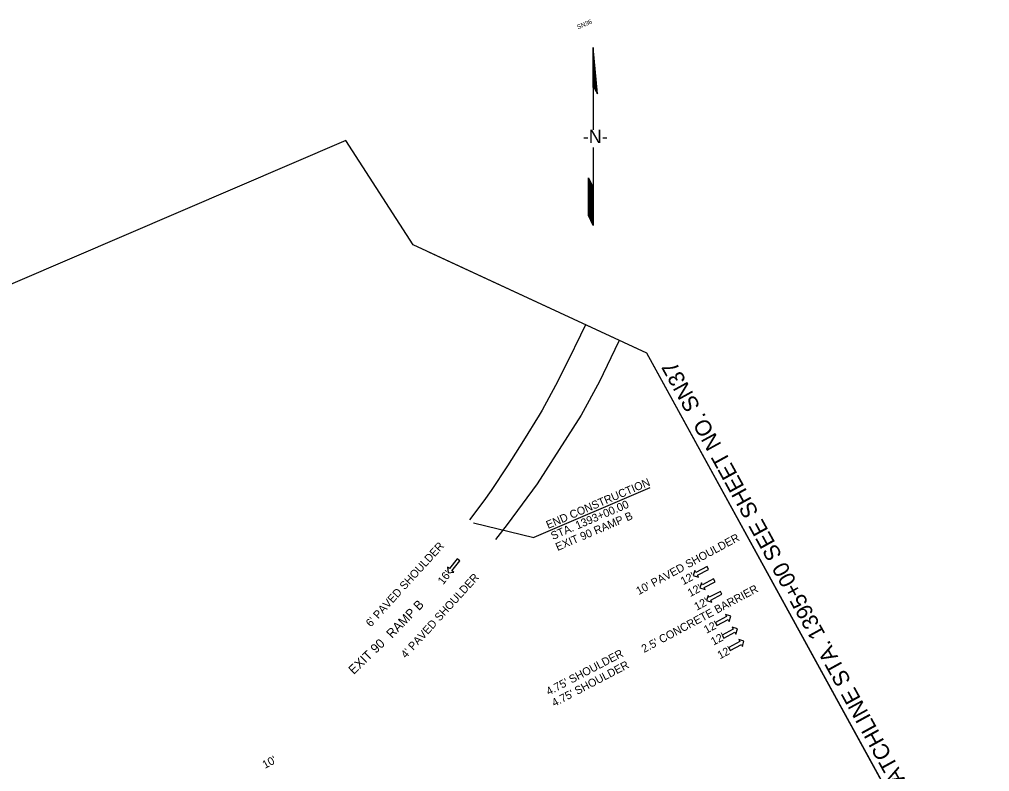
# Model space of a CAD drawing. Extents: x 1786955 to 1788674, y 1181944 to 1183335.
# Drawn here: x 1787825 to 1788674, y 1182676 to 1183335 of the extents above; entities that cross this region are included whole.
import ezdxf

# ---------------------------------------------------------------- set-up
doc = ezdxf.new("R2010")
doc.units = 0
for name, color, linetype in [('RD_EX_Road', 7, 'Continuous'), ('RD_PD_Final_LnLine', 7, 'Continuous'), ('RD_PD_Final_TX', 7, 'Continuous'), ('RD_SHT_MatchLine', 7, 'Continuous'), ('RD_SHT_ShtClip', 7, 'Continuous'), ('RD_SHT_TX', 7, 'Continuous'), ('RD_Sketch1', 7, 'Continuous'), ('RD_TX_RoadID', 7, 'Continuous')]:
    doc.layers.add(name, color=color, linetype=linetype)

# ---------------------------------------------------------------- blocks, each defined once
blk = doc.blocks.new('NA5')
at = {"layer": 'RD_Sketch1'}
for p, q in [((26.81, 30.64), (47.48, 65.89)), ((47.48, 65.89), (26.84, 37.43)), ((27.18, 37.55), (14.47, 19.81)), ((28.07, 38.27), (26.81, 30.64)), ((14.47, 19.81), (5.46, 7.23)), ((-3.53, -5.33), (-18.54, -26.28)), ((-30.56, -36.2), (-22.3, -24.68)), ((-22.3, -24.68), (-24.05, -33.97)), ((-18.54, -26.28), (-43.3, -60.85)), ((-41.56, -51.56), (-30.56, -36.2)), ((-43.3, -60.85), (-41.56, -51.56))]:
    blk.add_line(p, q, dxfattribs=at)
for points in [[(27.37, 37.79), (47.42, 65.79)], [(27.6, 37.95), (46.9, 64.9)], [(27.82, 38.1), (46.37, 64)], [(27.93, 37.45), (43.75, 59.53)], [(27.97, 37.66), (44.28, 60.42)], [(28, 37.87), (44.8, 61.32)], [(28.04, 38.08), (45.32, 62.21)], [(28.05, 38.26), (45.85, 63.11)], [(27.14, 37.64), (39.24, 54.53)], [(27.62, 35.55), (39.03, 51.48)], [(27.66, 35.76), (39.56, 52.37)], [(27.69, 35.97), (40.08, 53.27)], [(27.73, 36.18), (40.6, 54.16)], [(27.76, 36.39), (41.13, 55.06)], [(27.8, 36.6), (41.65, 55.95)], [(27.83, 36.82), (42.18, 56.85)], [(27.86, 37.03), (42.7, 57.74)], [(27.9, 37.24), (43.23, 58.63)], [(27.27, 33.44), (33.79, 42.54)], [(27.31, 33.65), (34.31, 43.43)], [(27.34, 33.86), (34.84, 44.32)], [(27.38, 34.07), (35.36, 45.22)], [(27.41, 34.28), (35.88, 46.11)], [(27.45, 34.5), (36.41, 47.01)], [(27.48, 34.71), (36.93, 47.9)], [(27.52, 34.92), (37.46, 48.8)], [(27.55, 35.13), (37.98, 49.69)], [(27.59, 35.34), (38.51, 50.58)], [(26.91, 37.48), (29.9, 41.66)], [(26.96, 31.54), (29.07, 34.49)], [(26.99, 31.75), (29.59, 35.38)], [(27.03, 31.96), (30.12, 36.27)], [(27.06, 32.18), (30.64, 37.17)], [(27.1, 32.39), (31.16, 38.06)], [(27.13, 32.6), (31.69, 38.96)], [(27.17, 32.81), (32.21, 39.85)], [(27.2, 33.02), (32.74, 40.75)], [(27.24, 33.23), (33.26, 41.64)], [(26.82, 30.7), (26.97, 30.91)], [(26.85, 30.91), (27.49, 31.8)], [(26.89, 31.12), (28.02, 32.7)], [(26.92, 31.33), (28.54, 33.59)], [(-41.68, -52.18), (-22.42, -25.3)], [(-41.64, -51.96), (-22.38, -25.08)], [(-41.6, -51.74), (-22.34, -24.86)], [(-43.28, -60.75), (-24.03, -33.87)], [(-43.24, -60.53), (-23.99, -33.65)], [(-43.2, -60.31), (-23.94, -33.43)], [(-43.16, -60.09), (-23.9, -33.21)], [(-43.12, -59.87), (-23.86, -32.99)], [(-43.08, -59.65), (-23.82, -32.77)], [(-43.04, -59.43), (-23.78, -32.55)], [(-43, -59.21), (-23.74, -32.33)], [(-42.95, -58.99), (-23.7, -32.11)], [(-42.91, -58.77), (-23.66, -31.89)], [(-42.87, -58.55), (-23.61, -31.67)], [(-42.83, -58.34), (-23.57, -31.45)], [(-42.79, -58.12), (-23.53, -31.23)], [(-42.75, -57.9), (-23.49, -31.01)], [(-42.71, -57.68), (-23.45, -30.79)], [(-42.67, -57.46), (-23.41, -30.57)], [(-42.63, -57.24), (-23.37, -30.35)], [(-42.58, -57.02), (-23.33, -30.13)], [(-42.54, -56.8), (-23.29, -29.91)], [(-42.5, -56.58), (-23.24, -29.69)], [(-42.46, -56.36), (-23.2, -29.47)], [(-42.42, -56.14), (-23.16, -29.25)], [(-42.38, -55.92), (-23.12, -29.03)], [(-42.34, -55.7), (-23.08, -28.81)], [(-42.3, -55.48), (-23.04, -28.59)], [(-42.25, -55.26), (-23, -28.37)], [(-42.21, -55.04), (-22.96, -28.15)], [(-42.17, -54.82), (-22.91, -27.93)], [(-42.13, -54.6), (-22.87, -27.71)], [(-42.09, -54.38), (-22.83, -27.49)], [(-42.05, -54.16), (-22.79, -27.27)], [(-42.01, -53.94), (-22.75, -27.05)], [(-41.97, -53.72), (-22.71, -26.83)], [(-41.93, -53.5), (-22.67, -26.62)], [(-41.88, -53.28), (-22.63, -26.4)], [(-41.84, -53.06), (-22.59, -26.18)], [(-41.8, -52.84), (-22.54, -25.96)], [(-41.76, -52.62), (-22.5, -25.74)], [(-41.72, -52.4), (-22.46, -25.52)]]:
    blk.add_lwpolyline(points, dxfattribs=at)
blk.add_text('-N-', height=11.811, rotation=324.3865, dxfattribs=at).set_placement((-8.85, 3.04))
blk = doc.blocks.new('SARRW2')
at = {"layer": 'RD_PD_Final_LnLine'}
blk.add_lwpolyline([(-12, 1.2), (-12, -1.2), (-2.83, -1.2), (-2.83, -2.83), (0, 0), (-2.83, 2.83), (-2.83, 1.2)], close=True, dxfattribs=at)

msp = doc.modelspace()

# ---------------------------------------------------------------- linework, layer by layer
at = {"layer": 'RD_EX_Road'}
for points in [[(1788319.97, 1183067.15), (1788315.67, 1183058.02), (1788304.86, 1183035.99), (1788293.7, 1183014.14), (1788282.19, 1182992.48), (1788279.59, 1182988.15), (1788265.9, 1182965.9), (1788251.87, 1182943.86), (1788237.52, 1182922.03), (1788231.08, 1182913.14), (1788218.59, 1182896.46)], [(1788349.49, 1183053.46), (1788348.91, 1183052.21), (1788332.22, 1183017.55), (1788316.31, 1182988.06), (1788296.87, 1182957.91), (1788277.65, 1182928.04), (1788251.42, 1182892.38), (1788241.3, 1182879.13)]]:
    msp.add_lwpolyline(points, dxfattribs=at)
at = {"layer": 'RD_PD_Final_TX'}
for p in [(1788376.36, 1182924.38), (1788222.01, 1182893.85)]:
    msp.add_line(p, (1788274.79, 1182880.98), dxfattribs=at)
at = {"layer": 'RD_SHT_MatchLine'}
for points in [[(1788373.62, 1183042.27), (1788325.13, 1183064.76), (1788182.93, 1183130.69)], [(1788610.29, 1182611.12), (1788482.57, 1182843.8), (1788373.62, 1183042.27)]]:
    msp.add_lwpolyline(points, dxfattribs=at)
at = {"layer": 'RD_SHT_ShtClip'}
msp.add_lwpolyline([(1788602.87, 1182624.64), (1788373.62, 1183042.27), (1788169.17, 1183137.08), (1788110.36, 1183228.48), (1786954.94, 1182732.25), (1787147.48, 1182122.09), (1787221.15, 1182060.45), (1787293.74, 1181944.03), (1787901.65, 1182166), (1788673.56, 1182495.86)], close=True, dxfattribs=at)

# ---------------------------------------------------------------- block references
at = {"layer": 'RD_PD_Final_LnLine'}
for p, xscale, yscale, rotation in [((1788199.94, 1182850.15), 1.1999999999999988, 1.1999999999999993, -128.28857510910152), ((1788414.3, 1182847.57), 1.1999999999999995, 1.2000000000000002, -151.9162429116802), ((1788420.05, 1182836.78), 1.1999999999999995, 1.2000000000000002, -151.9162429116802), ((1788425.95, 1182825.72), 1.1999999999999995, 1.2000000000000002, -151.9162429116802), ((1788447.03, 1182812.01), 1.1999999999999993, 1.2000000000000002, 28.08375708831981), ((1788452.93, 1182800.96), 1.1999999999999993, 1.2000000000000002, 28.08375708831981), ((1788458.68, 1182790.17), 1.1999999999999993, 1.2000000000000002, 28.08375708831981)]:
    msp.add_blockref('SARRW2', p, dxfattribs=dict(at, xscale=xscale, yscale=yscale, rotation=rotation))
at = {"layer": 'RD_SHT_MatchLine', "rotation": 35.61349782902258}
msp.add_blockref('NA5', (1788326.53, 1183228.92), dxfattribs=at)

# ---------------------------------------------------------------- texts
at = {"layer": 'RD_PD_Final_TX'}
for s, rotation, p in [('END CONSTRUCTION', 23.13854, (1788287.33, 1182888.4)), ('STA. 1393+00.00', 23.13854, (1788291.46, 1182878.75)), ('EXIT 90 RAMP B', 23.13854, (1788295.59, 1182869.09)), ("6' PAVED SHOULDER", 47.7243, (1788132.22, 1182802.13)), ("10' PAVED SHOULDER", 28.4839, (1788366.6, 1182830.47)), ("16'", 51.71142, (1788195.49, 1182839.15)), ("12'", 28.08376, (1788405.51, 1182839.11)), ("4' PAVED SHOULDER", 47.7243, (1788162.85, 1182774.64)), ("2.5' CONCRETE BARRIER", 28.27402, (1788371.26, 1182779.83)), ("12'", 28.08376, (1788411.65, 1182828.75)), ("12'", 28.08376, (1788417.4, 1182816.82)), ("12'", 28.08376, (1788425.81, 1182796.57)), ("12'", 28.08376, (1788431.95, 1182786.22)), ("12'", 28.08376, (1788437.7, 1182774.28)), ("4.75' SHOULDER", 27.71719, (1788287.81, 1182742.53)), ("4.75' SHOULDER", 27.71719, (1788292.77, 1182732.56)), ("10'", 28.66729, (1788039.61, 1182678.31))]:
    msp.add_text(s, height=7, rotation=rotation, dxfattribs=at).set_placement(p)
at = {"layer": 'RD_SHT_MatchLine'}
msp.add_text('MATCHLINE STA. 1395+00 SEE SHEET NO. SN37', height=14, rotation=118.76354, dxfattribs=at).set_placement((1788607.28, 1182656.08))
at = {"layer": 'RD_SHT_TX'}
msp.add_text('SN36', height=4, rotation=23.13854, dxfattribs=at).set_placement((1788313.5, 1183325.83))
at = {"layer": 'RD_TX_RoadID'}
for s, rotation, p in [('RAMP B', 45.74536, (1788150.63, 1182792.2)), ('EXIT 90', 43.64, (1788117.21, 1182760.58))]:
    msp.add_text(s, height=8, rotation=rotation, dxfattribs=at).set_placement(p)

doc.saveas('drawing.dxf')
